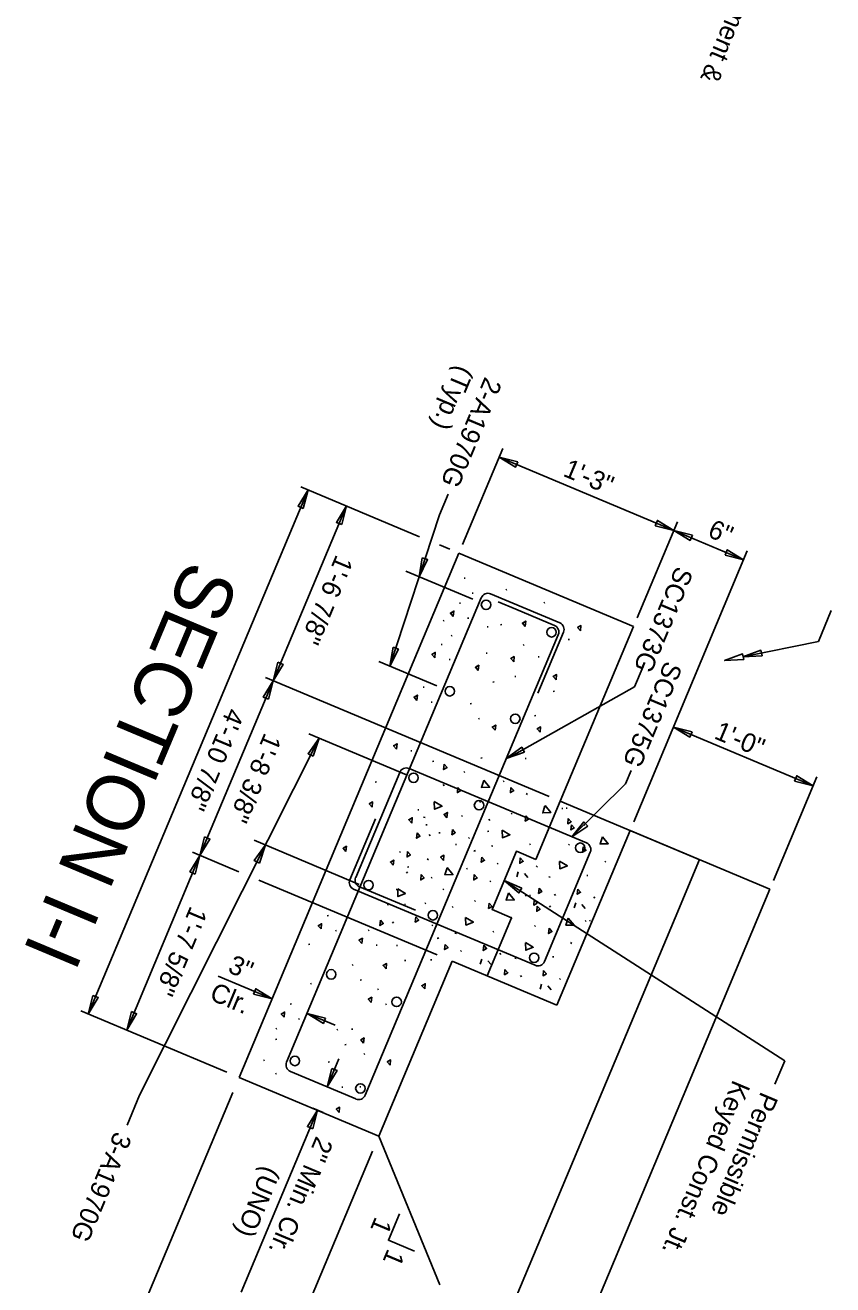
# Model space of a CAD drawing. Extents: x 1968564 to 1968711, y 796599 to 796794.
# Drawn here: x 1968619.69 to 1968641.02, y 796651.53 to 796684.77 of the extents above; entities that cross this region are included whole.
import ezdxf

# ---------------------------------------------------------------- set-up
doc = ezdxf.new("R2010")
doc.units = 0
for name, color, linetype in [('BR_AUTO DIMENSION', 7, 'Continuous'), ('BR_CONCRETE', 7, 'Continuous'), ('BR_DETAILS', 7, 'Continuous'), ('BR_REBAR', 7, 'Continuous'), ('BR_TEXT', 7, 'Continuous')]:
    doc.layers.add(name, color=color, linetype=linetype)

msp = doc.modelspace()

# ---------------------------------------------------------------- linework, layer by layer
at = {"layer": 'BR_AUTO DIMENSION'}
for p, q in [((1968631.241, 796671.063), (1968632.304, 796673.597)), ((1968632.207, 796673.367), (1968636.818, 796671.433)), ((1968627.16, 796672.504), (1968621.358, 796658.671)), ((1968630.104, 796671.268), (1968626.967, 796672.584)), ((1968628.174, 796672.078), (1968626.24, 796667.467)), ((1968630.628, 796671.848), (1968630.856, 796672.393)), ((1968629.322, 796667.851), (1968630.628, 796671.848)), ((1968635.852, 796669.129), (1968636.915, 796671.663)), ((1968635.852, 796669.129), (1968636.915, 796671.663)), ((1968636.818, 796671.433), (1968638.663, 796670.659)), ((1968630.902, 796670.934), (1968630.629, 796671.049)), ((1968635.762, 796663.744), (1968638.759, 796670.89)), ((1968629.742, 796670.359), (1968631.514, 796669.615)), ((1968640.635, 796668.506), (1968640.976, 796669.319)), ((1968638.644, 796668.096), (1968640.635, 796668.506)), ((1968629.033, 796667.972), (1968630.557, 796667.333)), ((1968635.782, 796667.302), (1968636.009, 796667.845)), ((1968626.24, 796667.467), (1968624.306, 796662.856)), ((1968633.53, 796664.41), (1968626.041, 796667.551)), ((1968635.782, 796667.302), (1968632.536, 796665.474)), ((1968636.81, 796666.243), (1968640.499, 796664.696)), ((1968627.452, 796665.952), (1968622.714, 796656.528)), ((1968627.183, 796666.065), (1968629.758, 796664.985)), ((1968635.547, 796664.748), (1968635.695, 796665.102)), ((1968639.451, 796662.197), (1968640.596, 796664.927)), ((1968635.547, 796664.748), (1968634.129, 796663.345)), ((1968625.736, 796663.257), (1968628.513, 796662.092)), ((1968624.306, 796662.856), (1968622.372, 796658.246)), ((1968625.335, 796662.425), (1968624.107, 796662.94)), ((1968630.572, 796660.229), (1968625.864, 796662.203)), ((1968632.342, 796662.195), (1968639.746, 796657.44)), ((1968624.788, 796659.672), (1968626.213, 796659.075)), ((1968626.321, 796659.331), (1968626.116, 796658.844)), ((1968625.019, 796657.135), (1968621.165, 796658.752)), ((1968627.873, 796658.378), (1968627.135, 796658.688)), ((1968627.975, 796657.486), (1968627.665, 796656.748)), ((1968639.746, 796657.44), (1968639.485, 796656.817)), ((1968622.714, 796656.528), (1968622.381, 796655.736)), ((1968625.174, 796656.597), (1968622.675, 796650.638)), ((1968625.393, 796651.33), (1968627.408, 796656.134)), ((1968627.288, 796656.184), (1968627.556, 796656.071)), ((1968628.863, 796655.05), (1968626.363, 796649.091))]:
    msp.add_line(p, q, dxfattribs=at)
for points in [[(1968632.698, 796673.242), (1968632.207, 796673.367), (1968632.64, 796673.104)], [(1968627.035, 796672.013), (1968627.16, 796672.504), (1968626.897, 796672.071)], [(1968628.049, 796671.588), (1968628.174, 796672.078), (1968627.911, 796671.646)], [(1968636.328, 796671.557), (1968636.818, 796671.433), (1968636.386, 796671.695)], [(1968637.308, 796671.309), (1968636.818, 796671.433), (1968637.25, 796671.17)], [(1968638.173, 796670.783), (1968638.663, 796670.659), (1968638.231, 796670.922)], [(1968630.177, 796670.71), (1968630.093, 796670.211), (1968630.319, 796670.663)], [(1968629.406, 796668.35), (1968629.322, 796667.851), (1968629.548, 796668.303)], [(1968638.664, 796668.029), (1968638.159, 796668.002), (1968638.634, 796668.176)], [(1968639.149, 796668.124), (1968638.644, 796668.096), (1968639.119, 796668.271)], [(1968626.364, 796667.957), (1968626.24, 796667.467), (1968626.502, 796667.899)], [(1968626.116, 796666.977), (1968626.24, 796667.467), (1968625.977, 796667.035)], [(1968637.301, 796666.119), (1968636.81, 796666.243), (1968637.243, 796665.981)], [(1968627.294, 796665.472), (1968627.452, 796665.952), (1968627.16, 796665.539)], [(1968632.872, 796665.578), (1968632.395, 796665.411), (1968632.802, 796665.71)], [(1968640.009, 796664.82), (1968640.499, 796664.696), (1968640.067, 796664.959)], [(1968634.545, 796663.632), (1968634.129, 796663.345), (1968634.443, 796663.742)], [(1968624.43, 796663.347), (1968624.306, 796662.856), (1968624.568, 796663.289)], [(1968625.876, 796662.652), (1968626.034, 796663.132), (1968625.742, 796662.719)], [(1968624.182, 796662.366), (1968624.306, 796662.856), (1968624.043, 796662.424)], [(1968632.806, 796661.996), (1968632.342, 796662.195), (1968632.727, 796661.868)], [(1968621.482, 796659.161), (1968621.358, 796658.671), (1968621.62, 796659.103)], [(1968625.723, 796659.199), (1968626.213, 796659.075), (1968625.781, 796659.337)], [(1968622.496, 796658.736), (1968622.372, 796658.246), (1968622.635, 796658.678)], [(1968627.625, 796658.564), (1968627.135, 796658.688), (1968627.567, 796658.425)], [(1968627.79, 796657.238), (1968627.665, 796656.748), (1968627.928, 796657.18)], [(1968627.283, 796655.643), (1968627.408, 796656.134), (1968627.145, 796655.701)]]:
    msp.add_lwpolyline(points, close=True, dxfattribs=at)
msp.add_lwpolyline([(1968629.972, 796652.413), (1968629.281, 796652.703), (1968629.571, 796653.395)], dxfattribs=at)
at = {"layer": 'BR_CONCRETE'}
for p, q in [((1968631.144, 796670.832), (1968625.343, 796657)), ((1968635.755, 796668.898), (1968631.144, 796670.832)), ((1968633.821, 796664.287), (1968635.755, 796668.898)), ((1968633.821, 796664.287), (1968633.177, 796662.75)), ((1968637.51, 796662.74), (1968633.821, 796664.287)), ((1968635.666, 796663.514), (1968633.732, 796658.903)), ((1968635.666, 796663.514), (1968639.354, 796661.967)), ((1968636.85, 796661.214), (1968637.493, 796662.748)), ((1968639.354, 796661.967), (1968639.037, 796661.209)), ((1968631.59, 796648.674), (1968636.85, 796661.214)), ((1968632.532, 796661.214), (1968631.888, 796659.677)), ((1968639.037, 796661.209), (1968633.452, 796647.893)), ((1968630.965, 796660.063), (1968629.032, 796655.452)), ((1968633.732, 796658.903), (1968630.965, 796660.063)), ((1968629.032, 796655.452), (1968625.343, 796657)), ((1968629.032, 796655.452), (1968630.638, 796651.526))]:
    msp.add_line(p, q, dxfattribs=at)
msp.add_lwpolyline([(1968632.532, 796661.214), (1968632.02, 796661.428), (1968632.664, 796662.965), (1968633.177, 796662.75)], dxfattribs=at)
at = {"layer": 'BR_DETAILS'}
for p, q in [((1968631.281, 796670.17), (1968631.311, 796670.176)), ((1968631.495, 796669.774), (1968631.524, 796669.78)), ((1968632.383, 796669.865), (1968632.412, 796669.871)), ((1968631.16, 796669.51), (1968631.19, 796669.515)), ((1968633.384, 796669.522), (1968633.413, 796669.527)), ((1968631.374, 796669.114), (1968631.404, 796669.12)), ((1968630.725, 796669.05), (1968630.754, 796669.056)), ((1968631.888, 796668.887), (1968631.918, 796668.892)), ((1968632.245, 796668.944), (1968632.274, 796668.95)), ((1968630.672, 796668.42), (1968630.701, 796668.425)), ((1968630.939, 796668.655), (1968630.968, 796668.66)), ((1968632.841, 796668.404), (1968632.871, 796668.41)), ((1968634.03, 796668.551), (1968634.06, 796668.556)), ((1968631.862, 796668.19), (1968631.892, 796668.195)), ((1968633.233, 796668.095), (1968633.262, 796668.1)), ((1968630.885, 796668.024), (1968630.915, 796668.03)), ((1968632.043, 796667.431), (1968632.073, 796667.437)), ((1968632.62, 796667.574), (1968632.649, 796667.58)), ((1968630.199, 796667.293), (1968630.229, 796667.299)), ((1968633.637, 796667.182), (1968633.667, 796667.187)), ((1968630.413, 796666.898), (1968630.442, 796666.904)), ((1968631.444, 796666.859), (1968631.474, 796666.864)), ((1968631.658, 796666.463), (1968631.687, 796666.469)), ((1968633.142, 796666.539), (1968633.172, 796666.545)), ((1968629.875, 796665.615), (1968629.904, 796665.62)), ((1968631.727, 796665.422), (1968631.756, 796665.428)), ((1968632.895, 796665.412), (1968632.924, 796665.417)), ((1968630.45, 796665.334), (1968630.479, 796665.34)), ((1968628.937, 796664.789), (1968628.967, 796664.795)), ((1968631.275, 796665.073), (1968631.303, 796665.043)), ((1968632.34, 796664.813), (1968632.31, 796664.807)), ((1968630.729, 796664.726), (1968630.757, 796664.696)), ((1968632.924, 796664.491), (1968632.952, 796664.461)), ((1968631.688, 796664.279), (1968631.716, 796664.249)), ((1968633.888, 796664.098), (1968633.859, 796664.093)), ((1968634.003, 796664.106), (1968633.973, 796664.1)), ((1968630.061, 796664.057), (1968630.09, 796664.062)), ((1968630.249, 796663.854), (1968630.213, 796663.864)), ((1968631.241, 796663.902), (1968631.211, 796663.896)), ((1968631.93, 796663.811), (1968631.958, 796663.781)), ((1968632.522, 796663.974), (1968632.55, 796663.944)), ((1968630.274, 796663.661), (1968630.304, 796663.667)), ((1968630.615, 796663.451), (1968630.645, 796663.456)), ((1968631.903, 796663.489), (1968631.932, 796663.495)), ((1968633.481, 796663.526), (1968633.509, 796663.497)), ((1968634.439, 796663.672), (1968634.467, 796663.642)), ((1968630.36, 796663.405), (1968630.388, 796663.375)), ((1968631.052, 796663.141), (1968631.082, 796663.147)), ((1968631.394, 796663.332), (1968631.422, 796663.302)), ((1968632.043, 796663.102), (1968632.006, 796663.112)), ((1968633.034, 796663.15), (1968633.004, 796663.144)), ((1968634.037, 796663.154), (1968634.065, 796663.124)), ((1968629.576, 796662.942), (1968629.605, 796662.948)), ((1968630.309, 796662.769), (1968630.337, 796662.739)), ((1968631.569, 796662.974), (1968631.539, 796662.969)), ((1968631.584, 796662.986), (1968631.554, 796662.98)), ((1968629.789, 796662.546), (1968629.819, 796662.552)), ((1968631.374, 796662.509), (1968631.344, 796662.503)), ((1968632.153, 796662.653), (1968632.181, 796662.623)), ((1968633.187, 796662.58), (1968633.216, 796662.55)), ((1968634.996, 796662.707), (1968635.024, 796662.677)), ((1968629.762, 796662.422), (1968629.79, 796662.392)), ((1968630.41, 796662.268), (1968630.439, 796662.273)), ((1968631.958, 796662.187), (1968631.986, 796662.158)), ((1968632.672, 796662.295), (1968632.713, 796662.422)), ((1968632.879, 796662.381), (1968632.963, 796662.278)), ((1968633.558, 796662.282), (1968633.522, 796662.293)), ((1968634.549, 796662.33), (1968634.519, 796662.324)), ((1968629.491, 796661.954), (1968629.521, 796661.96)), ((1968630.721, 796661.975), (1968630.749, 796661.945)), ((1968632.922, 796661.795), (1968632.893, 796661.789)), ((1968633.036, 796661.802), (1968633.007, 796661.796)), ((1968633.668, 796661.833), (1968633.696, 796661.803)), ((1968634.703, 796661.76), (1968634.731, 796661.73)), ((1968629.283, 796661.55), (1968629.247, 796661.56)), ((1968629.705, 796661.558), (1968629.734, 796661.564)), ((1968630.274, 796661.598), (1968630.245, 796661.592)), ((1968630.964, 796661.507), (1968630.992, 796661.478)), ((1968631.555, 796661.67), (1968631.584, 796661.64)), ((1968633.538, 796661.524), (1968633.566, 796661.495)), ((1968634.187, 796661.475), (1968634.228, 796661.602)), ((1968634.394, 796661.562), (1968634.478, 796661.459)), ((1968627.669, 796661.261), (1968627.699, 796661.267)), ((1968629.393, 796661.101), (1968629.421, 796661.071)), ((1968632.514, 796661.223), (1968632.543, 796661.193)), ((1968634.503, 796661.132), (1968634.474, 796661.126)), ((1968634.617, 796661.139), (1968634.588, 796661.133)), ((1968627.883, 796660.865), (1968627.912, 796660.871)), ((1968628.745, 796660.879), (1968628.775, 796660.885)), ((1968630.428, 796661.028), (1968630.456, 796660.998)), ((1968631.076, 796660.798), (1968631.04, 796660.808)), ((1968632.067, 796660.846), (1968632.038, 796660.84)), ((1968633.136, 796661.007), (1968633.164, 796660.977)), ((1968627.176, 796660.508), (1968627.206, 796660.513)), ((1968628.959, 796660.484), (1968628.988, 796660.489)), ((1968629.497, 796660.477), (1968629.526, 796660.483)), ((1968630.602, 796660.67), (1968630.573, 796660.665)), ((1968630.618, 796660.682), (1968630.588, 796660.676)), ((1968634.095, 796660.56), (1968634.123, 796660.53)), ((1968630.397, 796660.1), (1968630.426, 796660.105)), ((1968631.186, 796660.349), (1968631.214, 796660.319)), ((1968631.706, 796659.991), (1968631.747, 796660.118)), ((1968632.221, 796660.276), (1968632.249, 796660.246)), ((1968632.657, 796660.135), (1968632.621, 796660.145)), ((1968633.648, 796660.183), (1968633.619, 796660.177)), ((1968628.326, 796659.962), (1968628.356, 796659.968)), ((1968629.71, 796660.082), (1968629.74, 796660.087)), ((1968631.912, 796660.078), (1968631.997, 796659.974)), ((1968627.227, 796659.47), (1968627.256, 796659.476)), ((1968628.54, 796659.567), (1968628.569, 796659.572)), ((1968632.767, 796659.686), (1968632.795, 796659.656)), ((1968633.287, 796659.328), (1968633.328, 796659.455)), ((1968633.802, 796659.613), (1968633.83, 796659.583)), ((1968628.993, 796659.318), (1968629.023, 796659.324)), ((1968633.493, 796659.415), (1968633.578, 796659.311)), ((1968626.692, 796658.93), (1968626.721, 796658.936)), ((1968629.207, 796658.923), (1968629.236, 796658.928)), ((1968626.905, 796658.535), (1968626.935, 796658.541)), ((1968626.307, 796658.284), (1968626.337, 796658.29)), ((1968627.922, 796658.256), (1968627.951, 796658.262)), ((1968628.311, 796658.27), (1968628.34, 796658.276)), ((1968626.302, 796658.001), (1968626.332, 796658.007)), ((1968628.136, 796657.86), (1968628.165, 796657.866)), ((1968625.981, 796657.445), (1968626.011, 796657.451)), ((1968628.63, 796657.616), (1968628.659, 796657.622)), ((1968627.696, 796657.401), (1968627.725, 796657.407)), ((1968626.301, 796657.094), (1968626.331, 796657.1)), ((1968628.051, 796656.74), (1968628.081, 796656.745)), ((1968628.527, 796656.746), (1968628.556, 796656.752))]:
    msp.add_line(p, q, dxfattribs=at)
for points in [[(1968630.996, 796669.164), (1968630.92, 796669.25), (1968631.01, 796669.303), (1968630.996, 796669.164)], [(1968632.897, 796668.901), (1968632.821, 796668.987), (1968632.91, 796669.04), (1968632.897, 796668.901)], [(1968634.354, 796668.783), (1968634.277, 796668.87), (1968634.367, 796668.922), (1968634.354, 796668.783)], [(1968630.508, 796668.074), (1968630.431, 796668.16), (1968630.521, 796668.213), (1968630.508, 796668.074)], [(1968632.59, 796667.966), (1968632.514, 796668.052), (1968632.603, 796668.104), (1968632.59, 796667.966)], [(1968631.656, 796667.737), (1968631.579, 796667.823), (1968631.669, 796667.876), (1968631.656, 796667.737)], [(1968633.708, 796667.488), (1968633.632, 796667.575), (1968633.721, 796667.627), (1968633.708, 796667.488)], [(1968630.035, 796666.948), (1968629.959, 796667.034), (1968630.048, 796667.087), (1968630.035, 796666.948)], [(1968632.101, 796666.158), (1968632.025, 796666.244), (1968632.115, 796666.297), (1968632.101, 796666.158)], [(1968633.287, 796666.109), (1968633.21, 796666.195), (1968633.3, 796666.248), (1968633.287, 796666.109)], [(1968629.497, 796665.664), (1968629.42, 796665.751), (1968629.51, 796665.803), (1968629.497, 796665.664)], [(1968630.754, 796665.261), (1968630.831, 796665.175), (1968630.741, 796665.122), (1968630.754, 796665.261)], [(1968631.801, 796664.84), (1968631.954, 796664.654), (1968631.739, 796664.65), (1968631.8, 796664.836)], [(1968631.116, 796664.653), (1968631.192, 796664.567), (1968631.103, 796664.514), (1968631.116, 796664.653)], [(1968632.518, 796664.653), (1968632.594, 796664.566), (1968632.504, 796664.514), (1968632.518, 796664.653)], [(1968628.853, 796664.128), (1968628.776, 796664.215), (1968628.866, 796664.267), (1968628.853, 796664.128)], [(1968630.493, 796664.276), (1968630.7, 796664.153), (1968630.5, 796664.075), (1968630.493, 796664.271)], [(1968633.418, 796664.17), (1968633.571, 796663.985), (1968633.356, 796663.98), (1968633.417, 796664.167)], [(1968629.897, 796663.711), (1968629.82, 796663.797), (1968629.91, 796663.85), (1968629.897, 796663.711)], [(1968630.829, 796663.852), (1968630.752, 796663.939), (1968630.842, 796663.991), (1968630.829, 796663.852)], [(1968632.909, 796663.901), (1968632.985, 796663.815), (1968632.896, 796663.762), (1968632.909, 796663.901)], [(1968634.033, 796663.833), (1968634.109, 796663.747), (1968634.02, 796663.694), (1968634.033, 796663.833)], [(1968630.038, 796663.449), (1968630.115, 796663.363), (1968630.025, 796663.31), (1968630.038, 796663.449)], [(1968630.972, 796663.541), (1968631.048, 796663.454), (1968630.959, 796663.402), (1968630.972, 796663.541)], [(1968632.286, 796663.523), (1968632.493, 796663.401), (1968632.293, 796663.323), (1968632.286, 796663.519)], [(1968634.113, 796663.668), (1968634.19, 796663.582), (1968634.1, 796663.529), (1968634.113, 796663.668)], [(1968628.162, 796662.961), (1968628.085, 796663.047), (1968628.175, 796663.1), (1968628.162, 796662.961)], [(1968634.934, 796663.351), (1968635.086, 796663.165), (1968634.872, 796663.16), (1968634.932, 796663.347)], [(1968629.788, 796662.957), (1968629.864, 796662.871), (1968629.774, 796662.818), (1968629.788, 796662.957)], [(1968630.737, 796662.723), (1968630.66, 796662.809), (1968630.75, 796662.862), (1968630.737, 796662.723)], [(1968631.746, 796662.814), (1968631.823, 796662.728), (1968631.733, 796662.675), (1968631.746, 796662.814)], [(1968632.765, 796662.789), (1968632.842, 796662.702), (1968632.752, 796662.65), (1968632.765, 796662.789)], [(1968634.424, 796663.081), (1968634.501, 796662.995), (1968634.411, 796662.942), (1968634.424, 796663.081)], [(1968629.412, 796662.596), (1968629.335, 796662.683), (1968629.425, 796662.735), (1968629.412, 796662.596)], [(1968630.835, 796662.536), (1968630.987, 796662.351), (1968630.773, 796662.346), (1968630.833, 796662.533)], [(1968633.801, 796662.704), (1968634.008, 796662.581), (1968633.808, 796662.504), (1968633.801, 796662.7)], [(1968630.149, 796662.349), (1968630.226, 796662.263), (1968630.136, 796662.21), (1968630.149, 796662.349)], [(1968631.551, 796662.349), (1968631.628, 796662.262), (1968631.538, 796662.21), (1968631.551, 796662.349)], [(1968629.527, 796661.972), (1968629.733, 796661.849), (1968629.534, 796661.771), (1968629.527, 796661.968)], [(1968632.452, 796661.867), (1968632.604, 796661.681), (1968632.39, 796661.676), (1968632.45, 796661.863)], [(1968633.262, 796661.994), (1968633.338, 796661.908), (1968633.248, 796661.855), (1968633.262, 796661.994)], [(1968634.28, 796661.969), (1968634.357, 796661.883), (1968634.267, 796661.83), (1968634.28, 796661.969)], [(1968631.943, 796661.597), (1968632.019, 796661.511), (1968631.929, 796661.458), (1968631.943, 796661.597)], [(1968633.132, 796661.686), (1968633.209, 796661.599), (1968633.119, 796661.547), (1968633.132, 796661.686)], [(1968633.213, 796661.521), (1968633.289, 796661.434), (1968633.2, 796661.382), (1968633.213, 796661.521)], [(1968629.072, 796661.145), (1968629.148, 796661.059), (1968629.059, 796661.006), (1968629.072, 796661.145)], [(1968630.006, 796661.237), (1968630.082, 796661.15), (1968629.992, 796661.098), (1968630.006, 796661.237)], [(1968631.32, 796661.22), (1968631.527, 796661.097), (1968631.327, 796661.019), (1968631.32, 796661.215)], [(1968634.033, 796661.204), (1968634.185, 796661.018), (1968633.971, 796661.013), (1968634.031, 796661.2)], [(1968627.505, 796660.915), (1968627.429, 796661.002), (1968627.518, 796661.054), (1968627.505, 796660.915)], [(1968633.523, 796660.934), (1968633.6, 796660.848), (1968633.51, 796660.795), (1968633.523, 796660.934)], [(1968628.581, 796660.533), (1968628.505, 796660.62), (1968628.594, 796660.672), (1968628.581, 796660.533)], [(1968630.78, 796660.51), (1968630.857, 796660.424), (1968630.767, 796660.371), (1968630.78, 796660.51)], [(1968631.799, 796660.485), (1968631.875, 796660.398), (1968631.785, 796660.346), (1968631.799, 796660.485)], [(1968632.901, 796660.557), (1968633.107, 796660.434), (1968632.908, 796660.356), (1968632.9, 796660.552)], [(1968629.221, 796659.865), (1968629.144, 796659.952), (1968629.234, 796660.004), (1968629.221, 796659.865)], [(1968632.361, 796659.847), (1968632.438, 796659.761), (1968632.348, 796659.708), (1968632.361, 796659.847)], [(1968633.379, 796659.822), (1968633.456, 796659.735), (1968633.366, 796659.683), (1968633.379, 796659.822)], [(1968630.241, 796659.333), (1968630.165, 796659.419), (1968630.254, 796659.472), (1968630.241, 796659.333)], [(1968628.829, 796658.973), (1968628.752, 796659.059), (1968628.842, 796659.112), (1968628.829, 796658.973)], [(1968626.528, 796658.585), (1968626.451, 796658.671), (1968626.541, 796658.724), (1968626.528, 796658.585)], [(1968628.626, 796657.903), (1968628.55, 796657.989), (1968628.64, 796658.042), (1968628.626, 796657.903)], [(1968629.328, 796657.322), (1968629.252, 796657.409), (1968629.342, 796657.461), (1968629.328, 796657.322)], [(1968627.981, 796656.072), (1968627.904, 796656.158), (1968627.994, 796656.211), (1968627.981, 796656.072)]]:
    msp.add_lwpolyline(points, dxfattribs=at)
at = {"layer": 'BR_REBAR'}
for p, q in [((1968631.981, 796669.758), (1968633.807, 796668.992)), ((1968626.595, 796657.4), (1968631.736, 796669.657)), ((1968632.184, 796669.549), (1968632.645, 796669.355)), ((1968632.645, 796669.355), (1968633.666, 796668.927)), ((1968633.232, 796667.137), (1968633.907, 796668.747)), ((1968628.67, 796656.53), (1968633.767, 796668.682)), ((1968634.511, 796663.185), (1968629.827, 796665.15)), ((1968629.581, 796665.049), (1968628.418, 796662.275)), ((1968628.94, 796663.823), (1968628.265, 796662.213)), ((1968634.612, 796662.94), (1968633.403, 796660.058)), ((1968633.158, 796659.957), (1968628.361, 796661.969)), ((1968630.001, 796661.408), (1968628.518, 796662.03)), ((1968628.425, 796656.429), (1968626.696, 796657.155))]:
    msp.add_line(p, q, dxfattribs=at)
for centre in [(1968631.861, 796669.47), (1968633.59, 796668.745), (1968630.904, 796667.188), (1968632.633, 796666.463), (1968629.947, 796664.906), (1968631.676, 796664.181), (1968634.347, 796663.06), (1968628.758, 796662.072), (1968630.458, 796661.277), (1968633.129, 796660.156), (1968627.771, 796659.718), (1968629.5, 796658.992), (1968626.812, 796657.433), (1968628.542, 796656.708)]:
    msp.add_circle(centre, 0.125, dxfattribs=at)
for centre, start, end in [((1968631.909, 796669.585), 67.246, 157.246), ((1968633.594, 796668.754), 337.246, 67.246), ((1968633.734, 796668.819), 337.246, 67.246), ((1968629.754, 796664.977), 67.246, 157.246), ((1968634.439, 796663.012), 337.246, 67.246), ((1968628.437, 796662.14), 157.246, 247.246), ((1968628.591, 796662.203), 157.246, 247.246), ((1968633.23, 796660.13), 247.246, 337.246), ((1968626.768, 796657.328), 157.246, 247.246), ((1968628.497, 796656.602), 247.246, 337.246)]:
    msp.add_arc(centre, 0.188, start, end, dxfattribs=at)

# ---------------------------------------------------------------- texts
at = {"layer": 'BR_AUTO DIMENSION'}
for s, rotation, p in [('1\'-3"', 337.246, (1968633.868, 796672.879)), ('6"', 337.246, (1968637.685, 796671.278)), ('1\'-6 7/8"', 247.246, (1968627.906, 796670.816)), ('4\'-10 7/8"', 247.246, (1968625.032, 796666.778)), ('1\'-0"', 337.246, (1968637.857, 796665.953)), ('1\'-8 3/8"', 247.246, (1968626.015, 796666.115)), ('1\'-7 5/8"', 247.246, (1968624.057, 796661.544)), ('3"', 337.246, (1968625.016, 796659.785)), ('2" Min. Clr. ', 247.246, (1968627.377, 796655.471)), ('(UNO)', 247.246, (1968625.987, 796654.692))]:
    msp.add_text(s, height=0.5, rotation=rotation, dxfattribs=at).set_placement(p)
at = {"layer": 'BR_TEXT'}
for s, height, rotation, p in [('Roadway Pavement &', 0.49995, 247.246, (1968640.071, 796689.469)), ('(Typ.)', 0.4999, 247.246, (1968631.095, 796675.819)), ('2-A1970G', 0.4999, 247.246, (1968631.834, 796675.509)), ('SECTION I-I', 1.5, 247.246, (1968623.973, 796670.706)), ('SC1373G', 0.4999, 247.246, (1968636.884, 796670.518)), (' SC1375G', 0.4999, 247.246, (1968636.668, 796668.189)), ('Clr.', 0.5, 337.246, (1968624.531, 796659.06)), ('Keyed Const. Jt.', 0.49995, 247.246, (1968638.389, 796656.956)), ('Permissible', 0.49995, 247.246, (1968639.126, 796656.646)), ('3-A1970G', 0.4999, 247.246, (1968622.059, 796655.597)), ('SECTION G-G', 1.5, 247.246, (1968645.898, 796654.826)), ('1', 0.5, 247.246, (1968628.939, 796653.344)), ('1', 0.5, 247.246, (1968629.267, 796652.5))]:
    msp.add_text(s, height=height, rotation=rotation, dxfattribs=at).set_placement(p)

doc.saveas('drawing.dxf')
